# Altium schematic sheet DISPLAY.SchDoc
size A3; Revision: V1.2; SheetNumber: 5; SheetTotal: 10
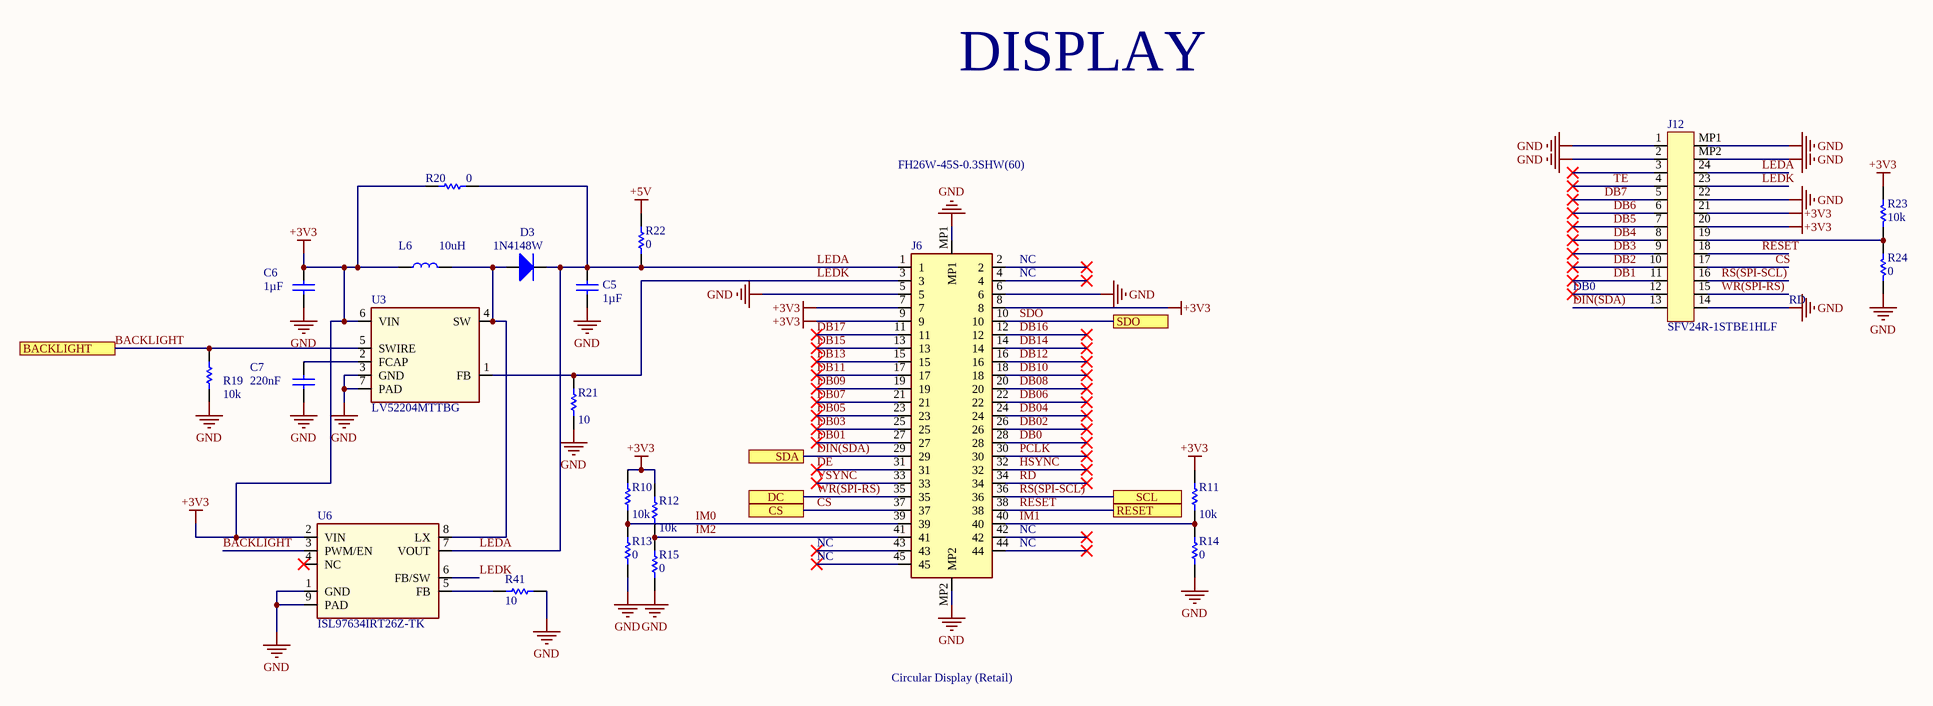
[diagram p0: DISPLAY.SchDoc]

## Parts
C5  value 1µF  [CAP-0805]  (hidden comment: GCM21BC72A105KE36L)
C6  value 1µF  [CAP-0402]  (hidden comment: C0402C105K8PACTU)
C7  value 220nF  [CAP-0402]  (hidden comment: C0402C224K9PACTU)
D3  1N4148W  [SOD123-1]
J6  FH26W-45S-0.3SHW(60)  [FH26W-45S-0.3SHW(60)-Footprint-1]
J12  SFV24R-1STBE1HLF  [SFV24R-1STBE1HLF-Footprint-1]
L6  SRR0604-100ML  [SRR0604-100ML-Footprint-1]  (value not drawn)
R10  value 10k  [RES-0402]  (hidden comment: CRCW040210K0FKED)
R11  value 10k  [RES-0402]  (hidden comment: CRCW040210K0FKED)
R12  value 10k  [RES-0402]  (hidden comment: CRCW040210K0FKED)
R13  value 0  [RES-0402]  (hidden comment: CRCW04020000Z0EDC)
R14  value 0  [RES-0402]  (hidden comment: CRCW04020000Z0EDC)
R15  value 0  [RES-0402]  (hidden comment: CRCW04020000Z0EDC)
R19  value 10k  [RES-0402]  (hidden comment: CRCW040210K0FKED)
R20  value 0  [RES-0402]  (hidden comment: CRCW04020000Z0EDC)
R21  value 10  [RES-0402]  (hidden comment: RC0402FR-0710RL)
R22  value 0  [RES-0402]  (hidden comment: CRCW04020000Z0EDC)
R23  value 10k  [RES-0402]  (hidden comment: CRCW040210K0FKED)
R24  value 0  [RES-0402]  (hidden comment: CRCW04020000Z0EDC)
R41  value 10  [RES-0402]  (hidden comment: RC0402FR-0710RL)
U3  LV52204MTTBG  [QFN65P200X200X80_HS-7L]
U6  ISL97634IRT26Z-TK  [PQFN0P300X200X80_HS-9L]

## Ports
BACKLIGHT, CS, DC, RESET, SCL, SDA, SDO

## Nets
+3V3: C6.2 J6.7 J6.8 J6.9 J12.20 J12.21 L6.1 R10.2 R11.2 R12.2 R20.2 R23.2 U3.6(VIN) U6.2(VIN)
+5V: R22.1
GND: C5.1 C6.1 C7.1 J6.5 J6.6 J6.MP1 J6.MP2 J12.1 J12.2 J12.14 J12.22 J12.MP1 J12.MP2 R13.1 R14.1 R15.1 R19.1 R21.1 R24.1 R41.1 U3.3(GND) U3.7(PAD) U6.1(GND) U6.9(PAD)
BACKLIGHT: R19.2 U3.5(SWIRE) U6.3(PWM/EN) ; port BACKLIGHT
CS: J6.37 J12.17 ; port CS
DB0: J6.28
DB01: J6.27
DB1: J12.11
DB02: J6.26
DB2: J12.10
DB03: J6.25
DB3: J12.9
DB04: J6.24
DB4: J12.8
DB05: J6.23
DB5: J12.7
DB06: J6.22
DB6: J12.6
DB07: J6.21
DB7: J12.5
DB08: J6.20
DB09: J6.19
DB10: J6.18
DB11: J6.17
DB12: J6.16
DB13: J6.15
DB14: J6.14
DB15: J6.13
DB16: J6.12
DB17: J6.11
DE: J6.31
DIN(SDA): J6.29 J12.13 ; port SDA
HSYNC: J6.32
IM0: J6.39 R10.1 R13.2
IM1: J6.40 R11.1 R14.2
IM2: J6.41 R12.1 R15.2
LEDA: C5.2 D3.C J6.1 J12.24 R20.1 R22.2 U6.7(VOUT)
LEDK: J6.3 J12.23 R21.2 U3.1(FB) U6.6(FB/SW)
PCLK: J6.30
RD: J6.34
RESET: J6.38 J12.18 ; port RESET
RS(SPI-SCL): J6.36 J12.16 ; port SCL
SDO: J6.10 ; port SDO
TE: J12.4
VSYNC: J6.33
WR(SPI-RS): J6.35 J12.15 ; port DC
NetC7_2: C7.2 U3.2(FCAP)
NetD3_A: D3.A L6.2 U3.4(SW) U6.8(LX)
NetJ12_19: J12.19 R23.1 R24.2
NetR41_2: R41.2 U6.5(FB)

Not connected (* = marked no-connect by the designer): J6 2* 4* 42* 43* 44* 45*; J12 3* 12*; U6 4(NC)*

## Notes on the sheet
- DISPLAY
- (near L6) 10uH
- (near J6) NC
- DB0
- RD
- NC
- Circular Display (Retail)

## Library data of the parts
C5 = C0084-A.9: CAP CHIP 0805 1uF 100V X7S 10%; Manufacturer: Murata; Code Arduino: C0084
C6 = C0017-A.11: CAP CHIP 0402 1uF 10V X5R 10%; Manufacturer: KEMET; Code Arduino: 0133
C7 = C0088-A.10: CAP CHIP 0402 220nF 6.3V X5R 10%; Manufacturer: KEMET; Code Arduino: C0088
D3 = D0029-A.2: DIODE FAST SMD 200mA 100V SOD123; Manufacturer: Vishay; Code Arduino: 0290; Device Type: Diode gen. Purp
J6 = J0028-A.3: CONN FPC/FFC 41POS .3MM; Manufacturer: Hirose; Pitch: 0.012inch; Current Rating: 200mA; Voltage Rating: 30V; Number of Positions: 45; Actuator Material: Nylon,Polyamide; Code Arduino: J0028
J12 = J0102-A.1: CONN FPC SMD SKT 24 POS 0.5mm RA SMD; Manufacturer: Amphenol FCI; Current Rating: 500mA; Code Arduino: J0102; Voltage Rating: 50V; Wire/Cable Type: Straight; Actuator Material: Glass,Polyphenylene; Insulation Resistance: 100MR; Number of Contacts: 24; Contact Resistance: 30mR; Contact Location: Bottom
L6 = I0013-A.5: FIXED IND 10UH 1.3A 120 MOHM SMD; Manufacturer: Bourns; Frequency: 30MHz; Tolerance: 20%; DC Resistance (DCR): 120mR; Test Frequency: 2.52MHz; Code Arduino: 0031
R10-R12 R19 R23 = R0003-A.11: RES CHIP 0402 10K 1% 1/16W; Manufacturer: Vishay; Code Arduino: 0136; Power: 63mW
R13-R15 R20 R22 R24 = R0000-A.11: RES CHIP 0402 0R 1/16W; Manufacturer: Vishay; Code Arduino: 0039; Power: 63mW; Tolerance: J
R21 R41 = R0170-A.10: RES CHIP 0402 10R 1/16W 1%; Manufacturer: Yageo; Power: 63mW; Working Voltage: 50V; Temperature Coefficient: 100ppm/°C; Code Arduino: R0170
U3 = U0125-A.8: IC LED BOOST DRIVER PWM DIMMING VIN 2V7 TO 5V5 VOUT MAX 40V; Manufacturer: ON Semiconductor; Number of Outputs: 1; Output Current per Channel: 700mA; Max Supply Voltage: 5.5V; Switching Frequency: 600kHz; Nominal Input Voltage (DC): 3.6V; Code Arduino: U0125; Dimming: PWM,Single-Wire; Max Output Voltage: 39V; Min Input Voltage: 2.7V; Min Output Voltage: 37V
U6 = U0264-A.4: IC WHITE LED DRIVER W/PW DIM 26V TDFN-EP-8; Manufacturer: Renesas; Code Arduino: U0264; Min Supply Voltage: 2.4V; Max Supply Voltage: 5.5V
